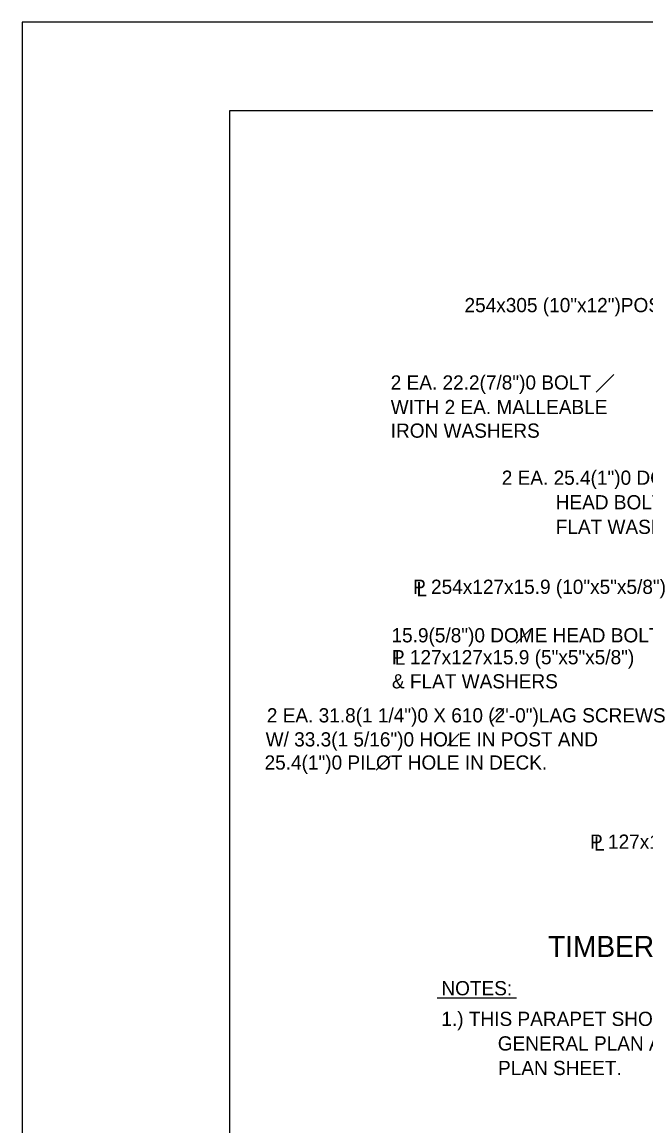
# Model space of a CAD drawing. Extents: x 0 to 36.3, y -66 to 0.
# Drawn here: x 0 to 5.26, y -9.31 to 0 of the extents above; entities that cross this region are included whole.
import ezdxf

# ---------------------------------------------------------------- set-up
doc = ezdxf.new("R2010")
doc.units = 0
for name, color, linetype in [('1', 7, 'Continuous'), ('2', 7, 'Continuous'), ('3', 7, 'Continuous'), ('62', 7, 'Continuous'), ('63', 7, 'Continuous')]:
    doc.layers.add(name, color=color, linetype=linetype)

msp = doc.modelspace()

# ---------------------------------------------------------------- linework, layer by layer
at = {"layer": '1'}
msp.add_lwpolyline([(1.75, -21.25), (33.25, -21.25), (33.25, -0.75), (1.75, -0.75)], close=True, dxfattribs=at)
at = {"layer": '3'}
for p, q in [((4.8422, -3.1232), (4.9923, -2.9732)), ((4.1687, -5.241), (4.2879, -5.1218)), ((3.9601, -5.8968), (4.0645, -5.7923)), ((3.5881, -6.1048), (3.6882, -6.0048)), ((2.9861, -6.3123), (3.1075, -6.191)), ((3.5018, -8.2322), (4.1709, -8.2322))]:
    msp.add_line(p, q, dxfattribs=at)
at = {"layer": '62'}
msp.add_line((0, 0), (0, 0), dxfattribs=at)
at = {"layer": '63'}
msp.add_lwpolyline([(0, -22), (34, -22), (34, 0), (0, 0)], close=True, dxfattribs=at)

# ---------------------------------------------------------------- texts
at = {"layer": '2'}
msp.add_text('TIMBER POST, BRIDGE RAIL AND CURB DETAIL', height=0.177167, dxfattribs=at).set_placement((4.4365, -7.8868))
at = {"layer": '3'}
for s, p in [('254x305 (10"x12")POST', (3.7323, -2.4477)), ('2 EA. 22.2(7/8")0 BOLT', (3.1097, -3.1005)), ('WITH 2 EA. MALLEABLE', (3.1097, -3.3077)), ('IRON WASHERS', (3.1097, -3.5067)), ('2 EA. 25.4(1")0 DOME', (4.0463, -3.9038)), ('HEAD BOLTS WITH', (4.5013, -4.111)), ('FLAT WASHERS', (4.5013, -4.3182)), ('P 254x127x15.9 (10"x5"x5/8")', (3.2983, -4.8241)), ('L', (3.3273, -4.8447)), ('15.9(5/8")0 DOME HEAD BOLT WITH', (3.1162, -5.2331)), ('P 127x127x15.9 (5"x5"x5/8")', (3.1197, -5.4182)), ('L', (3.1429, -5.4225)), ('& FLAT WASHERS', (3.1197, -5.6215)), ('2 EA. 31.8(1 1/4")0 X 610 (2\'-0")LAG SCREWS', (2.0647, -5.9084)), ('W/ 33.3(1 5/16")0 HOLE IN POST AND', (2.0546, -6.1113)), ('25.4(1")0 PILOT HOLE IN DECK.', (2.0454, -6.3066)), ('P 127x127x15.9 (5"x5"x5/8")', (4.7908, -6.9744)), ('L', (4.8255, -6.9904)), ('NOTES:', (3.537, -8.2106)), ('1.) THIS PARAPET SHOWN ON THE', (3.537, -8.4693)), ('GENERAL PLAN AND FRAMING', (4.0128, -8.6765)), ('PLAN SHEET.', (4.0149, -8.8837))]:
    msp.add_text(s, height=0.12, dxfattribs=at).set_placement(p)

doc.saveas('drawing.dxf')
